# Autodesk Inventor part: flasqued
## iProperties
Shininess: 21.0
Length Units: 11269
Angle Units: 11279
Time Units: 11290
Mass Units: 11283
Length Display Precision: 3
Angle Display Precision: 2
Compacted: True
Created: 2001-12
Part Number: flasqued
Material: Par défaut
Document SubType Name: Tôlerie
Designer: pichon
Density: 0.0
Volumn: 0.0
Area: 0.0
PropertySet Name: Model Information
Control State: 0
Master: False
Checked Out: False
Author: pichon
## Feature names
1. Arrondi de coin1
2. Extrusion1
3. Extrusion2
4. Congé1 [Fillet]
5. Extrusion3
6. Plaque1
7. Plaque2
8. Pli1
9. Plaque3
10. Pli2
